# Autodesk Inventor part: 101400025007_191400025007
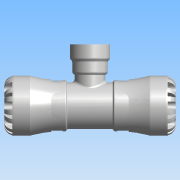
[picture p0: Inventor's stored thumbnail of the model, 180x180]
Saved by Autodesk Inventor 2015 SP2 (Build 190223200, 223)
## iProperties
Created: 2016-12
Part Number: 101400025007_191400025007
Material: PVC-Piping
Description: PLASSON TEE WITH THREADED FEMALE OFFTAKE 25X3/4" SERIES 1
Document SubType Name: Modeling
Designer: KIM
Mass: 664.223 g
Surface Area: 733.008 cm^2
Volume: 474.445 cm^3
Density: 1.4 g/cm^3
Appearance: Smooth - White
Author: KIM
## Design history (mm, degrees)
derived "1014.ipt"
feature "Solid1::1014.ipt"
tag "TaggingFeature1"
body "Solid1"
other parameters: "d1" = 20.16, "d2" = 25, "d3" = 31.25, "d4" = 47, "d8" = 39.95, "d13" = 6.3, "d14" = 6.3, "d15" = 0, "d17" = 360 deg, "d19" = 8 deg, "d20" = 0.5, "d21" = 0.5, "d22" = 8 deg, "d24" = 0, "d26" = 360 deg, "d33" = 4.7, "d43" = 36.66, "d51" = 0.47, "d54" = 8.75, "d55" = 5.5, "d57" = 12.348, "d58" = 0, "d74" = 0, "d77" = 2.08333, "d78" = 48, "d79" = 36.66, "d80" = 134, "d82" = 0.5, "d115" = 360 deg, "d139" = 6.3, "d140" = 0, "d142" = 360 deg, "d207" = 90 deg, "d228" = 7.4375, "d247" = 0.94, "d248" = 2.88, "d266" = 0, "d268" = 24.117, "d270" = 3.61755, "d271" = 6, "d274" = 1.80878, "d275" = 48, "d276" = 2.4117, "d277" = 2.4117, "d278" = 2.4117, "d279" = 2.4117, "d281" = 0, "d282" = 18, "d_" = 25, "E_" = 47, "l_" = 48, "A_" = 48, "H_" = 134, "Rp_" = 24.117, "l_2" = 18, "d9" = 7.875, "d11" = 47, "d12" = 31.25
